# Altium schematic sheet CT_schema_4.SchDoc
size 187 x 156 mm
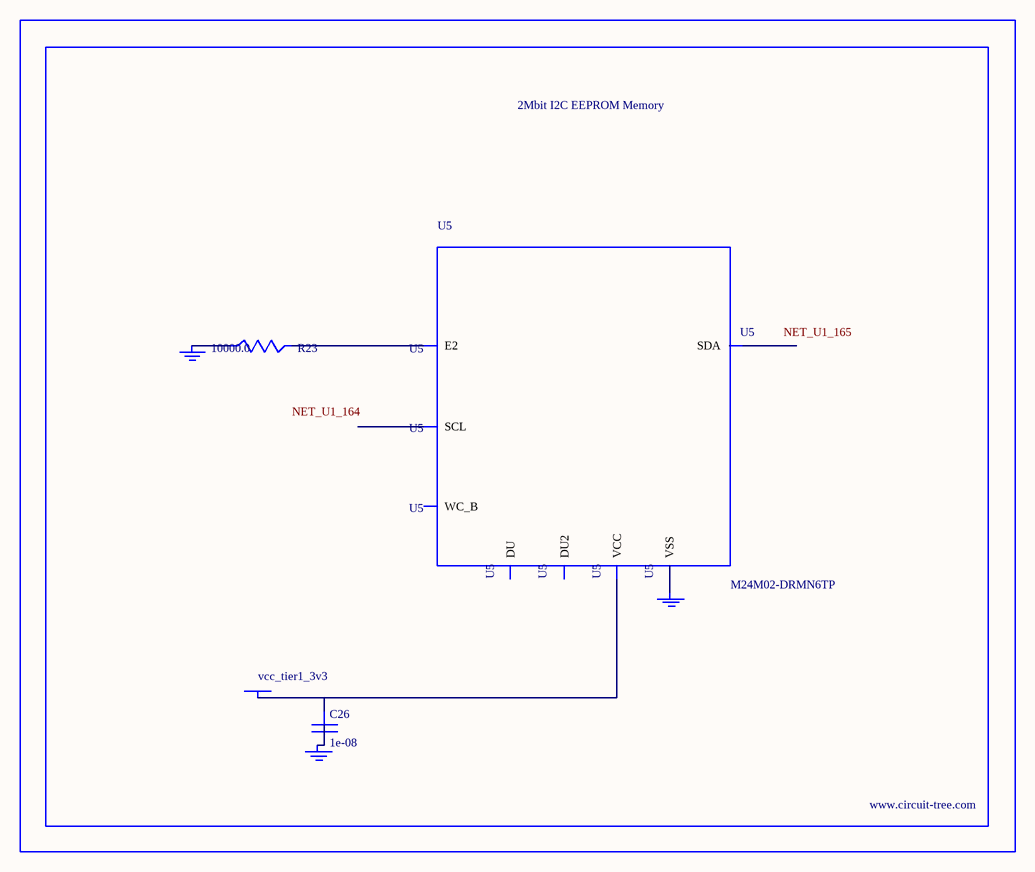
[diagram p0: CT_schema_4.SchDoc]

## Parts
BORDER3  (no value)
C26  1e-08  [C0402]
GND_INSTANCE_3_0  (no value)
GND_INSTANCE_3_1  (no value)
GND_INSTANCE_3_2  (no value)
POWER_INSTANCE_3_0  vcc_tier1_3v3
R23  10000.0  [R0603]
U5  M24M02-DRMN6TP  [SOIC-8]

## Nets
NetC26_1: C26.1 POWER_INSTANCE_3_0.0(PWR) U5.8(VCC)
NetC26_2: C26.2 GND_INSTANCE_3_1.0(GND)
NetGND_INSTANCE_3_0_0: GND_INSTANCE_3_0.0(GND) R23.1
NetGND_INSTANCE_3_2_0: GND_INSTANCE_3_2.0(GND) U5.4(VSS)
NetR23_2: R23.2 U5.3(E2)

Not connected (* = marked no-connect by the designer): U5 1(DU) 2(DU2) 5(SDA) 6(SCL) 7(WC_B)

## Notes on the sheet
- Labels drawn without touching a wire or pin: NET_U1_164, NET_U1_165

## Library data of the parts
BORDER3 = BORDER_PAGE3
C26 = C0402C103K3RAC
GND_INSTANCE_3_0-GND_INSTANCE_3_2 = GND
POWER_INSTANCE_3_0 = PWR
R23 = RC0603JR-0710KL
